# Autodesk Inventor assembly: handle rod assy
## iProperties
Author: Elise Moss
Created: 2001-09
Part Number: handle rod assy
Document SubType Name: Assembly
Designer: Elise Moss
Control State: 0
Master: False
Checked Out: False
PropertySet Name: Design Tracking Control
Length Units: 11272
Angle Units: 11279
Time Units: 11290
Mass Units: 11286
Shininess: 3
Angle Display Precision: 2
Document Length Units: 11272
Document Angle Units: 11286
Document Time Units: 11279
Document Mass Units: 11290
Document Length Units Precision: 3
Document Angle Units Precision: 2
Compacted: False
PropertySet Name: _Private Model Information
Density: 0.0
Volumn: 0.0
Area: 0.0
PropertySet Name: Model Information
